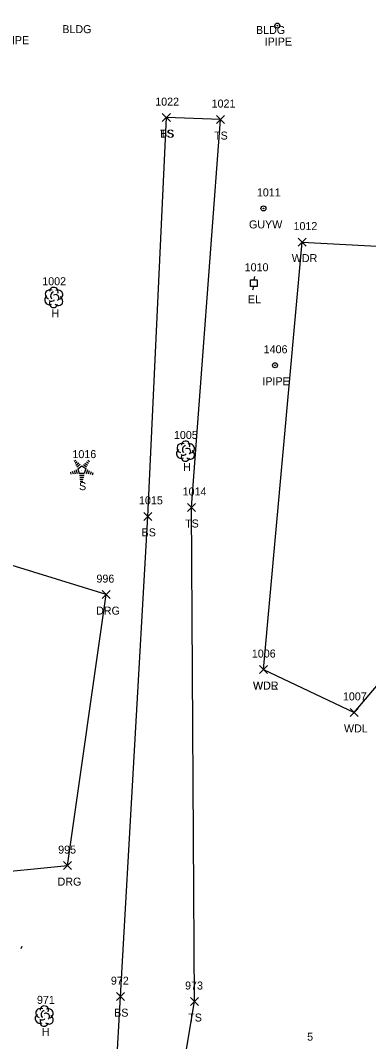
# Model space of a CAD drawing. Extents: x 1767353 to 1772625, y 740790 to 747702.
# Drawn here: x 1770245.8 to 1770332.7, y 742414.3 to 742669.5 of the extents above; entities that cross this region are included whole.
import ezdxf

# ---------------------------------------------------------------- set-up
doc = ezdxf.new("R2010")
doc.units = 0
for name, color, linetype in [('C_I', 7, 'Continuous'), ('L_A', 7, 'Continuous'), ('L_I', 7, 'Continuous'), ('L_TIC', 7, 'Continuous'), ('LAWA', 7, 'Continuous'), ('LELB', 7, 'Continuous'), ('LTC', 7, 'Continuous'), ('LTD', 7, 'Continuous'), ('M_A', 7, 'Continuous'), ('M_I', 7, 'Continuous'), ('MPIP', 7, 'Continuous'), ('R_A', 7, 'Continuous'), ('R_I', 7, 'Continuous'), ('R_TIC', 7, 'Continuous'), ('RDG', 7, 'Continuous'), ('U_A', 7, 'Continuous'), ('U_I', 7, 'Continuous'), ('UEPT', 7, 'Continuous'), ('UPGW', 7, 'Continuous')]:
    doc.layers.add(name, color=color, linetype=linetype)

msp = doc.modelspace()

# ---------------------------------------------------------------- linework, layer by layer
at = {"layer": 'L_TIC'}
for points in [[(1770281.22, 742644.21), (1770283.22, 742646.21)], [(1770283.22, 742644.21), (1770281.22, 742646.21)], [(1770281.22, 742644.21), (1770283.22, 742646.21)], [(1770283.22, 742644.21), (1770281.22, 742646.21)], [(1770294.74, 742643.73), (1770296.74, 742645.73)], [(1770296.74, 742643.73), (1770294.74, 742645.73)], [(1770315.18, 742613.11), (1770317.18, 742615.11)], [(1770317.18, 742613.11), (1770315.18, 742615.11)], [(1770287.5, 742546.79), (1770289.5, 742548.79)], [(1770289.5, 742546.79), (1770287.5, 742548.79)], [(1770276.6, 742544.58), (1770278.6, 742546.58)], [(1770278.6, 742544.58), (1770276.6, 742546.58)], [(1770305.48, 742506.29), (1770307.48, 742508.29)], [(1770307.48, 742506.29), (1770305.48, 742508.29)], [(1770305.48, 742506.29), (1770307.48, 742508.29)], [(1770307.48, 742506.29), (1770305.48, 742508.29)], [(1770328.16, 742495.59), (1770330.16, 742497.59)], [(1770330.16, 742495.59), (1770328.16, 742497.59)], [(1770269.74, 742424.56), (1770271.74, 742426.56)], [(1770271.74, 742424.56), (1770269.74, 742426.56)], [(1770288.26, 742423.34), (1770290.26, 742425.34)], [(1770290.26, 742423.34), (1770288.26, 742425.34)]]:
    msp.add_lwpolyline(points, dxfattribs=at)
at = {"layer": 'LAWA'}
for points in [[(1770306.48, 742507.29), (1770316.18, 742614.11), (1770369.05, 742611.22), (1770392.48, 742651.21), (1770395.28, 742680.85), (1770432.3, 742733.17), (1770478.55, 742800.68), (1770491.83, 742862.01), (1770523.03, 742843.62)], [(1770306.48, 742507.29), (1770329.16, 742496.59), (1770362.8, 742536.32), (1770458.24, 742720.87), (1770495.95, 742787.49), (1770523.03, 742843.62)]]:
    msp.add_lwpolyline(points, dxfattribs=at)
at = {"layer": 'LELB'}
for points in [[(1770162.33, 742204.96), (1770182.69, 742228.32), (1770195.35, 742241.18), (1770232.57, 742237.56), (1770259.25, 742271.37), (1770269.87, 742307.96), (1770289.26, 742424.34), (1770288.5, 742547.79), (1770295.74, 742644.73), (1770282.22, 742645.21)], [(1770251.29, 742275.75), (1770264.27, 742310.68), (1770270.74, 742425.56), (1770277.6, 742545.58), (1770282.22, 742645.21)]]:
    msp.add_lwpolyline(points, dxfattribs=at)
at = {"layer": 'LTC'}
for p, q in [((1770259.23, 742559.34), (1770259.58, 742559.6)), ((1770262.63, 742559.58), (1770263.05, 742559.28)), ((1770258.72, 742556.84), (1770258.93, 742556.19)), ((1770259.17, 742557.05), (1770259.44, 742556.22)), ((1770259.44, 742558.88), (1770259.97, 742559.26)), ((1770259.63, 742557.27), (1770259.96, 742556.25)), ((1770259.65, 742558.41), (1770260.35, 742558.92)), ((1770259.86, 742557.94), (1770260.73, 742558.58)), ((1770260.08, 742557.49), (1770261.09, 742558.22)), ((1770260.08, 742557.49), (1770260.47, 742556.3)), ((1770261.09, 742558.22), (1770262.09, 742557.5)), ((1770261.51, 742558.54), (1770262.32, 742557.95)), ((1770262.09, 742557.5), (1770261.7, 742556.3)), ((1770261.88, 742558.88), (1770262.56, 742558.39)), ((1770262.53, 742557.23), (1770262.19, 742556.19)), ((1770262.25, 742559.23), (1770262.8, 742558.83)), ((1770262.97, 742556.98), (1770262.68, 742556.09)), ((1770258.26, 742556.62), (1770258.41, 742556.15)), ((1770261.7, 742556.3), (1770260.47, 742556.3)), ((1770261.66, 742555.8), (1770260.52, 742555.8)), ((1770261.58, 742555.3), (1770260.59, 742555.3)), ((1770261.49, 742554.8), (1770260.66, 742554.8)), ((1770261.41, 742554.3), (1770260.73, 742554.3)), ((1770263.42, 742556.73), (1770263.18, 742556)), ((1770263.86, 742556.48), (1770263.67, 742555.9)), ((1770246.1, 742438.06), (1770245.92, 742437.49))]:
    msp.add_line(p, q, dxfattribs=at)
at = {"layer": 'LTD'}
for p, q in [((1770254.08, 742600.33), (1770254.08, 742600.33)), ((1770254.08, 742600.33), (1770254.08, 742600.33)), ((1770286.98, 742561.92), (1770286.98, 742561.92)), ((1770286.98, 742561.92), (1770286.98, 742561.92)), ((1770251.71, 742420.76), (1770251.71, 742420.76)), ((1770251.71, 742420.76), (1770251.71, 742420.76))]:
    msp.add_line(p, q, dxfattribs=at)
for centre in [(1770254.13, 742601.76), (1770287.02, 742563.35), (1770251.75, 742422.19)]:
    msp.add_arc(centre, 1.05, 335.5272, 180.9563, dxfattribs=at)
for centre, major_axis, ratio, start_param, end_param in [((1770253, 742599.62), (0.58, -1.04), 0.959034, 3.141593, 6.283185), ((1770253.29, 742600.99), (1.21, -0.51), 0.895232, 1.570796, 4.712389), ((1770253.87, 742600.79), (-0.208, -0.792), 0.645439, 3.141593, 6.283185), ((1770254.58, 742600.16), (-0.5, 0.667), 0.989748, 3.141593, 6.283185), ((1770255.08, 742599.49), (-1.09, 0.79), 0.841452, 1.570796, 4.712389), ((1770255.12, 742600.91), (-1.14, -0.48), 0.949671, 1.570796, 4.712389), ((1770254.08, 742598.83), (0.26, 1.06), 0.942809, 1.570796, 4.712389), ((1770253.62, 742599.58), (-0.625, -0.083), 0.423636, 0, 3.141593), ((1770285.89, 742561.21), (0.58, -1.04), 0.959034, 3.141593, 6.283185), ((1770286.18, 742562.58), (1.21, -0.51), 0.895232, 1.570796, 4.712389), ((1770286.77, 742562.38), (-0.208, -0.792), 0.645439, 3.141593, 6.283185), ((1770287.48, 742561.75), (-0.5, 0.667), 0.989748, 3.141593, 6.283185), ((1770287.98, 742561.08), (-1.09, 0.79), 0.841452, 1.570796, 4.712389), ((1770288.02, 742562.5), (-1.14, -0.48), 0.949671, 1.570796, 4.712389), ((1770286.98, 742560.42), (0.26, 1.06), 0.942809, 1.570796, 4.712389), ((1770286.52, 742561.17), (-0.625, -0.083), 0.423636, 0, 3.141593), ((1770250.92, 742421.43), (1.21, -0.51), 0.895232, 1.570796, 4.712389), ((1770251.5, 742421.22), (-0.208, -0.792), 0.645439, 3.141593, 6.283185), ((1770252.75, 742421.34), (-1.14, -0.48), 0.949671, 1.570796, 4.712389), ((1770250.62, 742420.05), (0.58, -1.04), 0.959034, 3.141593, 6.283185), ((1770251.71, 742419.26), (0.26, 1.06), 0.942809, 1.570796, 4.712389), ((1770251.25, 742420.01), (-0.625, -0.083), 0.423636, 0, 3.141593), ((1770252.21, 742420.59), (-0.5, 0.667), 0.989748, 3.141593, 6.283185), ((1770252.71, 742419.93), (-1.09, 0.79), 0.841452, 1.570796, 4.712389)]:
    msp.add_ellipse(centre, major_axis=major_axis, ratio=ratio, start_param=start_param, end_param=end_param, dxfattribs=at)
at = {"layer": 'MPIP'}
for centre, radius in [((1770309.94, 742668.21), 0.625), ((1770309.94, 742668.21), 0.0833), ((1770309.36, 742583.33), 0.625), ((1770309.36, 742583.33), 0.0833)]:
    msp.add_circle(centre, radius, dxfattribs=at)
at = {"layer": 'R_TIC'}
for points in [[(1770266.19, 742525.02), (1770268.19, 742527.02)], [(1770268.19, 742525.02), (1770266.19, 742527.02)], [(1770256.57, 742457.3), (1770258.57, 742459.3)], [(1770258.57, 742457.3), (1770256.57, 742459.3)]]:
    msp.add_lwpolyline(points, dxfattribs=at)
at = {"layer": 'RDG'}
msp.add_lwpolyline([(1770204.13, 742500.37), (1770216.45, 742489.14), (1770211.23, 742464.55), (1770235.77, 742456.2), (1770257.57, 742458.3), (1770267.19, 742526.02), (1770193.8, 742548.72), (1770201.83, 742582.22)], dxfattribs=at)
at = {"layer": 'UEPT'}
for p, q in [((1770304.23, 742605.48), (1770304.07, 742604.65)), ((1770303.23, 742602.98), (1770303.23, 742604.65)), ((1770303.23, 742604.65), (1770304.9, 742604.65)), ((1770304.9, 742602.98), (1770303.23, 742602.98)), ((1770303.82, 742602.15), (1770304.07, 742602.98)), ((1770304.07, 742603.82), (1770304.07, 742603.82)), ((1770304.9, 742604.65), (1770304.9, 742602.98))]:
    msp.add_line(p, q, dxfattribs=at)
at = {"layer": 'UPGW'}
for radius in [0.625, 0.0833]:
    msp.add_circle((1770306.47, 742622.53), radius, dxfattribs=at)

# ---------------------------------------------------------------- texts
at = {"layer": 'C_I'}
msp.add_text('5', height=2, dxfattribs=at).set_placement((1770317.38, 742414.56))
msp.add_text('5', height=2, dxfattribs=at).set_placement((1770317.38, 742414.56))
msp.add_text('5', height=2, dxfattribs=at).set_placement((1770317.38, 742414.56))
msp.add_text('5', height=2, dxfattribs=at).set_placement((1770317.38, 742414.56))
msp.add_text('5', height=2, dxfattribs=at).set_placement((1770317.38, 742414.56))
msp.add_text('5', height=2, dxfattribs=at).set_placement((1770317.38, 742414.56))
msp.add_text('5', height=2, dxfattribs=at).set_placement((1770317.38, 742414.56))
msp.add_text('5', height=2, dxfattribs=at).set_placement((1770317.38, 742414.56))
msp.add_text('5', height=2, dxfattribs=at).set_placement((1770317.38, 742414.56))
msp.add_text('5', height=2, dxfattribs=at).set_placement((1770317.38, 742414.56))
msp.add_text('5', height=2, dxfattribs=at).set_placement((1770317.38, 742414.56))
msp.add_text('5', height=2, dxfattribs=at).set_placement((1770317.38, 742414.56))
msp.add_text('5', height=2, dxfattribs=at).set_placement((1770317.38, 742414.56))
msp.add_text('5', height=2, dxfattribs=at).set_placement((1770317.38, 742414.56))
msp.add_text('5', height=2, dxfattribs=at).set_placement((1770317.38, 742414.56))
at = {"layer": 'L_A'}
for s, p in [('BLDG', (1770256.24, 742666.32)), ('BLDG', (1770304.61, 742666.11)), ('TS', (1770280.63, 742640.21)), ('BS', (1770280.66, 742640.21)), ('TS', (1770294.14, 742639.73)), ('WDR', (1770313.54, 742609.11)), ('H', (1770253.51, 742595.33)), ('H', (1770286.41, 742556.92)), ('S', (1770260.42, 742552.13)), ('TS', (1770286.9, 742542.79)), ('BS', (1770276.04, 742540.58)), ('WDR', (1770303.84, 742502.29)), ('WDL', (1770303.89, 742502.29)), ('WDL', (1770326.58, 742491.59)), ('BS', (1770269.19, 742420.56)), ('TS', (1770287.67, 742419.34)), ('H', (1770251.14, 742415.76))]:
    msp.add_text(s, height=2, dxfattribs=at).set_placement(p)
at = {"layer": 'L_I'}
for s, p in [('1022', (1770279.45, 742648.21)), ('1022', (1770279.45, 742648.21)), ('1021', (1770293.53, 742647.73)), ('1012', (1770313.98, 742617.11)), ('1002', (1770251.23, 742603.33)), ('1005', (1770284.12, 742564.92)), ('1016', (1770258.77, 742560.13)), ('1014', (1770286.29, 742550.79)), ('1015', (1770275.39, 742548.58)), ('1006', (1770303.57, 742510.29)), ('1006', (1770303.57, 742510.29)), ('1007', (1770326.31, 742499.59)), ('972', (1770268.38, 742428.56)), ('973', (1770286.9, 742427.34)), ('971', (1770249.91, 742423.76))]:
    msp.add_text(s, height=2, dxfattribs=at).set_placement(p)
at = {"layer": 'LTC'}
msp.add_text('.', height=1.04, rotation=270, dxfattribs=at).set_placement((1770260.98, 742557.24))
at = {"layer": 'M_A'}
for p in [(1770241.13, 742663.57), (1770306.78, 742663.21), (1770306.2, 742578.33)]:
    msp.add_text('IPIPE', height=2, dxfattribs=at).set_placement(p)
at = {"layer": 'M_I'}
msp.add_text('1406', height=2, dxfattribs=at).set_placement((1770306.53, 742586.33))
at = {"layer": 'R_A'}
for p in [(1770264.68, 742521.02), (1770255.06, 742453.3)]:
    msp.add_text('DRG', height=2, dxfattribs=at).set_placement(p)
at = {"layer": 'R_I'}
for s, p in [('996', (1770264.77, 742529.02)), ('995', (1770255.21, 742461.3))]:
    msp.add_text(s, height=2, dxfattribs=at).set_placement(p)
at = {"layer": 'U_A'}
for s, p in [('GUYW', (1770302.86, 742617.53)), ('EL', (1770302.6, 742598.82))]:
    msp.add_text(s, height=2, dxfattribs=at).set_placement(p)
at = {"layer": 'U_I'}
for s, p in [('1011', (1770304.83, 742625.53)), ('1010', (1770301.78, 742606.82))]:
    msp.add_text(s, height=2, dxfattribs=at).set_placement(p)

doc.saveas('drawing.dxf')
